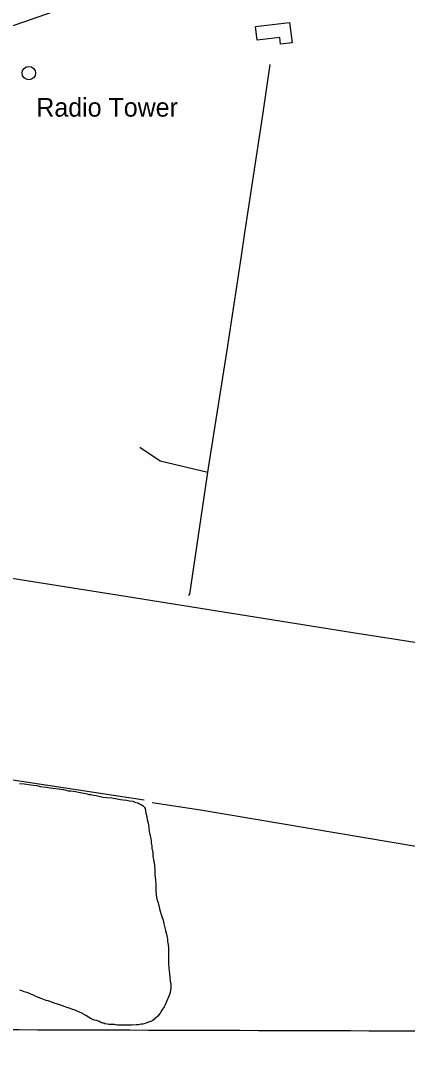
# Model space of a CAD drawing. Extents: x 3161514 to 3199414, y 831166 to 856601.
# Drawn here: x 3168099 to 3169818, y 842565 to 847172 of the extents above; entities that cross this region are included whole.
import ezdxf

# ---------------------------------------------------------------- set-up
doc = ezdxf.new("R2010")
doc.units = 0
for name, color, linetype in [('V-BLDG-OTLN', 7, 'Continuous'), ('V-GRID-MAJR', 7, 'Continuous'), ('V-SITE-VEGE', 7, 'Continuous'), ('V-TOPO-SHOR', 7, 'Continuous'), ('V-TOPO-TOWR', 7, 'Continuous'), ('V-TOPO-TOWR-IDEN', 7, 'Continuous')]:
    doc.layers.add(name, color=color, linetype=linetype)

msp = doc.modelspace()

# ---------------------------------------------------------------- linework, layer by layer
at = {"layer": 'V-BLDG-OTLN'}
msp.add_lwpolyline([(3169143.498, 847146.405), (3169294.124, 847165.06), (3169305.312, 847074.7050000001), (3169254.358, 847068.395), (3169250.645, 847098.38), (3169150.971, 847086.034)], close=True, dxfattribs=at)
at = {"layer": 'V-GRID-MAJR'}
msp.add_spline([(3165722.25, 842695.223), (3170954.554, 842678.861), (3176186.862, 842663.26), (3181419.1720000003, 842648.42), (3186651.484, 842634.341), (3191883.798, 842621.023), (3197116.113, 842608.466), (3197116.114, 842608.466)], degree=3, dxfattribs=at)
at = {"layer": 'V-SITE-VEGE'}
for points in [[(3168094.424, 843781.857), (3168114.847, 843779.87), (3168153.965, 843774.2170000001), (3168170.9930000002, 843773.13), (3168186.271, 843768.659), (3168213.484, 843764.877), (3168229.6350000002, 843762.0970000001), (3168256.011, 843759.179), (3168289.179, 843754.46), (3168299.38, 843752.615), (3168310.418, 843749.91), (3168321.482, 843748.902), (3168342.744, 843746.051), (3168356.343, 843743.309), (3168364.84, 843741.486), (3168371.631, 843739.6900000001), (3168380.1380000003, 843738.72), (3168394.585, 843735.965), (3168403.074, 843733.29), (3168411.577, 843732.322), (3168424.322, 843729.59), (3168434.521, 843727.7440000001), (3168446.426, 843725.876), (3168465.11, 843721.359)], [(3168465.11, 843721.359), (3168481.285, 843720.283), (3168504.255, 843717.41), (3168543.362, 843710.908), (3168554.423, 843709.902), (3168570.574, 843707.123), (3168582.481, 843705.255), (3168597.792, 843703.338), (3168607.1040000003, 843698.951), (3168619.836, 843695.365), (3168626.605, 843691.865), (3168635.907, 843686.625), (3168644.367, 843682.248), (3168647.716, 843677.941), (3168650.227, 843674.496), (3168651.881, 843671.066), (3168654.296, 843660.807), (3168655.863, 843650.559), (3168659.895, 843634.3150000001), (3168661.423, 843621.512), (3168666.3140000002, 843605.253), (3168667.059, 843597.5750000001), (3168670.92, 843568.549), (3168674.069, 843549.761), (3168677.311, 843537.786), (3168678.852, 843525.834), (3168679.574, 843516.452), (3168681.967, 843504.49), (3168682.677, 843494.2540000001), (3168686.679, 843475.451), (3168687.295, 843458.402), (3168690.386, 843435.351), (3168693.583, 843419.971), (3168694.934, 843394.389), (3168695.551, 843377.338), (3168697.755, 843351.746), (3168700.065, 843333.818), (3168700.54, 843306.542), (3168701.973, 843286.925), (3168705.111, 843267.282), (3168710, 843251.025), (3168716.463, 843225.3740000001), (3168719.717, 843214.251), (3168723.778, 843199.708), (3168727.0700000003, 843191.142), (3168731.9560000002, 843174.885), (3168735.143, 843158.65), (3168743.251, 843128.715), (3168747.275, 843111.618), (3168749.63, 843097.1), (3168751.265, 843091.963), (3168751.953, 843080.025), (3168754.308, 843065.505), (3168756.653, 843050.137), (3168756.1720000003, 843015.206), (3168756.741, 842994.747), (3168756.555, 842981.115), (3168757.124, 842960.658), (3168759.514, 842948.6950000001), (3168761.693, 842921.398), (3168763.9930000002, 842902.6190000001), (3168767.225, 842889.795), (3168766.125, 842871.914), (3168763.301, 842852.353), (3168759.705, 842838.769), (3168749.151, 842815.055), (3168742.1040000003, 842798.112), (3168736.859, 842788.81), (3168727.279, 842773.604), (3168719.435, 842760.931), (3168709.023, 842747.4400000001), (3168698.682, 842739.062), (3168686.6010000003, 842728.15), (3168684.023, 842726.481), (3168680.603, 842725.676), (3168672.036, 842722.387), (3168660.039, 842717.439), (3168653.188, 842714.978), (3168642.065, 842711.723), (3168634.398, 842711.828), (3168628.424, 842711.06), (3168622.435, 842709.438), (3168612.2120000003, 842709.579), (3168593.434, 842707.279), (3168527.8340000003, 842708.184), (3168516.781, 842710.042), (3168507.409, 842710.171), (3168491.234, 842711.246), (3168485.27, 842711.328), (3168472.528, 842714.06), (3168468.288, 842715.823), (3168464.883, 842715.868), (3168455.558, 842719.405), (3168447.95, 842723.772), (3168445.416, 842725.51), (3168437.798, 842729.025), (3168426.732, 842730.028), (3168419.102, 842732.691), (3168413.173, 842735.329), (3168388.666, 842750.154), (3168375.991, 842757.996)], [(3168375.991, 842757.996), (3168371.781, 842761.463), (3168364.148, 842764.123), (3168341.274, 842773.812), (3168331.097, 842777.362), (3168314.14, 842783.561), (3168310.756, 842785.312), (3168304.805, 842786.246), (3168296.332, 842789.7710000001), (3168273.448, 842798.608), (3168247.971, 842804.926), (3168220.849, 842815.522), (3168213.194, 842816.481), (3168190.3200000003, 842826.1680000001), (3168178.451, 842830.593), (3168173.362, 842832.367), (3168166.5810000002, 842835.017), (3168155.577, 842840.28), (3168147.105, 842843.807), (3168135.259, 842849.935), (3168125.935, 842853.474), (3168114.044, 842856.191), (3168108.115, 842858.829), (3168095.382, 842862.4130000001)]]:
    msp.add_lwpolyline(points, dxfattribs=at)
at = {"layer": 'V-TOPO-SHOR'}
msp.add_line((3167521.3871475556, 843879.8193499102), (3168648.7644062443, 843709.2916973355), dxfattribs=at)
for points in [[(3167966.484809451, 847117.056007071), (3168356.1136294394, 847252.0006227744), (3168369.4180281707, 847255.8018795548), (3168382.722426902, 847250.0999943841), (3168396.0268256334, 847252.0006227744), (3168401.728710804, 847269.106278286), (3168873.084551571, 847432.5603198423), (3168949.1096871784, 847455.3678605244)], [(3168845.344894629, 844618.3777711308), (3168851.660733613, 844623.1146503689), (3168933.7666404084, 845185.2243199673), (3169017.4515069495, 845707.8599959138), (3169079.0309370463, 846116.8105701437), (3169094.820534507, 846228.9167121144), (3169176.926441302, 846762.6051062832), (3169208.505636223, 846977.3436317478)], [(3168629.027409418, 845276.8039852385), (3168719.0281149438, 845216.8035148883), (3168930.6087209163, 845166.2768030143)], [(3167881.038434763, 844722.0673072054), (3168537.1864239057, 844618.4649931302), (3169575.6762864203, 844453.1946349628), (3170841.104551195, 844255.8568938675), (3170804.1037247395, 843935.1830645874), (3170747.3691241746, 843473.9060947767), (3170661.0338624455, 842788.15744447), (3170614.1661489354, 842450.2165628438)], [(3168683.5015206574, 843696.660019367), (3168898.2400461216, 843665.0808244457), (3170110.8811310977, 843459.8160574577), (3170546.6740210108, 843396.6576676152), (3170669.832881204, 843371.3943116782)]]:
    msp.add_lwpolyline(points, dxfattribs=at)
at = {"layer": 'V-TOPO-TOWR'}
msp.add_line((3168135.646, 846939.642), (3168135.646, 846939.642), dxfattribs=at)
msp.add_circle((3168135.646, 846939.642), 30.000000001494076, dxfattribs=at)

# ---------------------------------------------------------------- texts
at = {"layer": 'V-TOPO-TOWR-IDEN'}
msp.add_text('Radio Tower', height=82.99983200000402, dxfattribs=at).set_placement((3168168.8066256, 846746.133480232))

doc.saveas('drawing.dxf')
